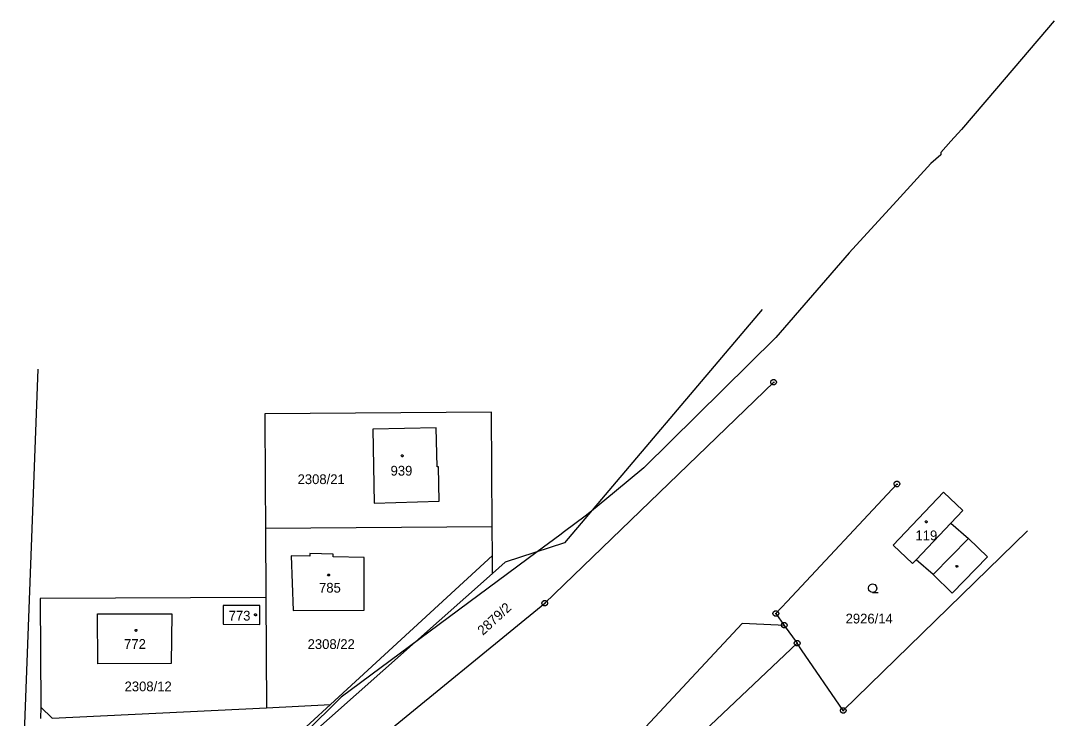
# Model space of a CAD drawing. Extents: x -760611 to -758411, y -1176479 to -1174807.
# Drawn here: x -758591.4 to -758411.4, y -1174928.5 to -1174806.9 of the extents above; entities that cross this region are included whole.
import ezdxf

# ---------------------------------------------------------------- set-up
doc = ezdxf.new("R2010")
doc.units = 0
for name, color, linetype in [('1', 7, 'Continuous'), ('11', 7, 'Continuous'), ('12', 7, 'Continuous'), ('2', 7, 'Continuous'), ('3', 7, 'Continuous'), ('4', 7, 'Continuous'), ('5', 7, 'Continuous'), ('8', 7, 'Continuous')]:
    doc.layers.add(name, color=color, linetype=linetype)

msp = doc.modelspace()

# ---------------------------------------------------------------- linework, layer by layer
at = {"layer": '1'}
for p, q in [((-758462.28, -1174857.27), (-758496.7, -1174897.94)), ((-758591.43, -1174949.22), (-758588.38, -1174867.67)), ((-758500.14, -1174908.44), (-758460.25, -1174869.94)), ((-758509.4, -1174875.14), (-758548.88, -1174875.41)), ((-758548.88, -1174875.41), (-758548.81, -1174887.41)), ((-758509.28, -1174895.15), (-758509.4, -1174875.14)), ((-758519.02, -1174877.9), (-758530.07, -1174878.13)), ((-758530.07, -1174878.13), (-758529.83, -1174890.98)), ((-758518.9, -1174884.67), (-758519.02, -1174877.9)), ((-758518.66, -1174884.67), (-758518.9, -1174884.67)), ((-758518.54, -1174890.66), (-758518.66, -1174884.67)), ((-758548.81, -1174887.41), (-758548.77, -1174895.41)), ((-758438.77, -1174887.67), (-758457.92, -1174908.13)), ((-758439.43, -1174898.33), (-758430.69, -1174889.1)), ((-758430.69, -1174889.1), (-758427.32, -1174892.29)), ((-758529.83, -1174890.98), (-758518.54, -1174890.66)), ((-758427.32, -1174892.29), (-758429.41, -1174894.49)), ((-758509.28, -1174895.15), (-758548.77, -1174895.41)), ((-758548.77, -1174895.41), (-758548.7, -1174907.41)), ((-758509.25, -1174900.15), (-758509.28, -1174895.15)), ((-758429.41, -1174894.49), (-758426.31, -1174897.14)), ((-758416.04, -1174895.82), (-758448.12, -1174927.13)), ((-758426.31, -1174897.14), (-758423, -1174900.38)), ((-758496.7, -1174897.94), (-758507.04, -1174901.3)), ((-758436.07, -1174901.52), (-758439.43, -1174898.33)), ((-758541.08, -1174900.26), (-758544.33, -1174900.19)), ((-758544.33, -1174900.19), (-758543.94, -1174909.68)), ((-758541.07, -1174899.78), (-758541.08, -1174900.26)), ((-758537.01, -1174899.88), (-758541.07, -1174899.78)), ((-758537.48, -1174926.06), (-758509.25, -1174900.15)), ((-758537.02, -1174900.36), (-758537.01, -1174899.88)), ((-758531.61, -1174900.48), (-758537.02, -1174900.36)), ((-758531.57, -1174909.63), (-758531.61, -1174900.48)), ((-758509.23, -1174903.24), (-758509.25, -1174900.15)), ((-758435.45, -1174900.87), (-758436.07, -1174901.52)), ((-758432.48, -1174903.46), (-758435.45, -1174900.87)), ((-758423, -1174900.38), (-758429.18, -1174906.69)), ((-758507.04, -1174901.3), (-758509.23, -1174903.24)), ((-758429.18, -1174906.69), (-758432.48, -1174903.46)), ((-758548.7, -1174907.41), (-758588.06, -1174907.59)), ((-758588.06, -1174907.59), (-758587.91, -1174926.56)), ((-758548.7, -1174907.41), (-758548.59, -1174926.64)), ((-758457.92, -1174908.13), (-758459.88, -1174910.23)), ((-758556.13, -1174908.84), (-758556.15, -1174912.09)), ((-758549.74, -1174908.83), (-758556.13, -1174908.84)), ((-758549.76, -1174912.13), (-758549.74, -1174908.83)), ((-758543.94, -1174909.68), (-758531.57, -1174909.63)), ((-758542.58, -1174943.09), (-758500.14, -1174908.44)), ((-758578.05, -1174910.27), (-758565.08, -1174910.27)), ((-758578.01, -1174919), (-758578.05, -1174910.27)), ((-758565.08, -1174910.27), (-758565.21, -1174918.94)), ((-758459.88, -1174910.23), (-758458.4, -1174912.29)), ((-758556.15, -1174912.09), (-758549.76, -1174912.13)), ((-758465.75, -1174911.99), (-758489.89, -1174937.8)), ((-758459.45, -1174912.25), (-758465.75, -1174911.99)), ((-758458.4, -1174912.29), (-758459.45, -1174912.25)), ((-758458.4, -1174912.29), (-758456.16, -1174915.41)), ((-758456.16, -1174915.41), (-758473.44, -1174931.75)), ((-758455.39, -1174916.53), (-758456.16, -1174915.41)), ((-758448.12, -1174927.13), (-758455.39, -1174916.53)), ((-758565.21, -1174918.94), (-758578.01, -1174919)), ((-758548.59, -1174926.64), (-758537.48, -1174926.06)), ((-758546.66, -1174934.51), (-758537.48, -1174926.06)), ((-758587.91, -1174926.56), (-758587.96, -1174928.54)), ((-758587.91, -1174926.56), (-758585.96, -1174928.44)), ((-758585.96, -1174928.44), (-758548.59, -1174926.64))]:
    msp.add_line(p, q, dxfattribs=at)
at = {"layer": '11'}
msp.add_lwpolyline([(-758411.36, -1174806.94), (-758421.45, -1174818.76), (-758427.54, -1174825.91), (-758429.37, -1174827.93), (-758431.14, -1174829.89), (-758431.14, -1174830.31), (-758432.86, -1174831.8), (-758438.19, -1174837.7), (-758447.12, -1174847.39), (-758459.9, -1174862.13), (-758482.88, -1174884.87), (-758487.98, -1174889.07), (-758492.01, -1174892.39), (-758493.08, -1174893.28), (-758496.7, -1174895.96), (-758497.52, -1174896.57), (-758501.45, -1174899.48), (-758535.6, -1174924.8), (-758541.98, -1174931.12)], dxfattribs=at)
at = {"layer": '12'}
for p, q in [((-758519.02, -1174877.9), (-758530.07, -1174878.13)), ((-758530.07, -1174878.13), (-758529.83, -1174890.98)), ((-758518.9, -1174884.67), (-758519.02, -1174877.9)), ((-758518.66, -1174884.67), (-758518.9, -1174884.67)), ((-758518.54, -1174890.66), (-758518.66, -1174884.67)), ((-758439.43, -1174898.33), (-758430.69, -1174889.1)), ((-758430.69, -1174889.1), (-758427.32, -1174892.29)), ((-758529.83, -1174890.98), (-758518.54, -1174890.66)), ((-758427.32, -1174892.29), (-758429.41, -1174894.49)), ((-758429.41, -1174894.49), (-758435.45, -1174900.87)), ((-758436.07, -1174901.52), (-758439.43, -1174898.33)), ((-758541.08, -1174900.26), (-758544.33, -1174900.19)), ((-758544.33, -1174900.19), (-758543.94, -1174909.68)), ((-758541.07, -1174899.78), (-758541.08, -1174900.26)), ((-758537.01, -1174899.88), (-758541.07, -1174899.78)), ((-758537.02, -1174900.36), (-758537.01, -1174899.88)), ((-758531.61, -1174900.48), (-758537.02, -1174900.36)), ((-758531.57, -1174909.63), (-758531.61, -1174900.48)), ((-758435.45, -1174900.87), (-758436.07, -1174901.52)), ((-758556.13, -1174908.84), (-758556.15, -1174912.09)), ((-758549.74, -1174908.83), (-758556.13, -1174908.84)), ((-758549.76, -1174912.13), (-758549.74, -1174908.83)), ((-758543.94, -1174909.68), (-758531.57, -1174909.63)), ((-758578.05, -1174910.27), (-758565.08, -1174910.27)), ((-758578.01, -1174919), (-758578.05, -1174910.27)), ((-758565.08, -1174910.27), (-758565.21, -1174918.94)), ((-758556.15, -1174912.09), (-758549.76, -1174912.13)), ((-758565.21, -1174918.94), (-758578.01, -1174919))]:
    msp.add_line(p, q, dxfattribs=at)
at = {"layer": '3'}
msp.add_lwpolyline([(-758443, -1174906.56), (-758443.38, -1174906.46), (-758443.65, -1174906.19), (-758443.75, -1174905.82), (-758443.65, -1174905.45), (-758443.38, -1174905.18), (-758443.01, -1174905.08), (-758442.64, -1174905.18), (-758442.37, -1174905.45), (-758442.27, -1174905.83), (-758442.37, -1174906.21), (-758442.64, -1174906.48), (-758443.02, -1174906.58), (-758442.02, -1174906.58)], dxfattribs=at)
at = {"layer": '4'}
for p, q in [((-758429.41, -1174894.49), (-758435.45, -1174900.87)), ((-758426.31, -1174897.14), (-758432.48, -1174903.46)), ((-758509.23, -1174903.24), (-758545.16, -1174935.1))]:
    msp.add_line(p, q, dxfattribs=at)
at = {"layer": '5'}
for points in [[(-758524.95, -1174882.58), (-758524.85, -1174882.6), (-758524.8, -1174882.69), (-758524.78, -1174882.75), (-758524.8, -1174882.84), (-758524.88, -1174882.91), (-758524.95, -1174882.92), (-758525.04, -1174882.89), (-758525.1, -1174882.83), (-758525.12, -1174882.75), (-758525.1, -1174882.66), (-758525.02, -1174882.59)], [(-758433.68, -1174894.08), (-758433.58, -1174894.1), (-758433.53, -1174894.19), (-758433.51, -1174894.25), (-758433.53, -1174894.34), (-758433.61, -1174894.41), (-758433.68, -1174894.42), (-758433.77, -1174894.39), (-758433.83, -1174894.33), (-758433.85, -1174894.25), (-758433.83, -1174894.16), (-758433.75, -1174894.09)], [(-758428.25, -1174901.88), (-758428.16, -1174902.03), (-758428.25, -1174902.18), (-758428.43, -1174902.18), (-758428.52, -1174902.03), (-758428.43, -1174901.88)], [(-758537.78, -1174903.35), (-758537.68, -1174903.37), (-758537.63, -1174903.46), (-758537.61, -1174903.52), (-758537.63, -1174903.61), (-758537.71, -1174903.68), (-758537.78, -1174903.69), (-758537.87, -1174903.66), (-758537.93, -1174903.6), (-758537.95, -1174903.52), (-758537.93, -1174903.43), (-758537.85, -1174903.36)], [(-758550.52, -1174910.29), (-758550.42, -1174910.31), (-758550.37, -1174910.4), (-758550.35, -1174910.46), (-758550.37, -1174910.55), (-758550.45, -1174910.62), (-758550.52, -1174910.63), (-758550.61, -1174910.6), (-758550.67, -1174910.54), (-758550.69, -1174910.46), (-758550.67, -1174910.37), (-758550.59, -1174910.3)], [(-758571.32, -1174913), (-758571.22, -1174913.02), (-758571.17, -1174913.11), (-758571.15, -1174913.17), (-758571.17, -1174913.26), (-758571.25, -1174913.33), (-758571.32, -1174913.34), (-758571.41, -1174913.31), (-758571.47, -1174913.25), (-758571.49, -1174913.17), (-758571.47, -1174913.08), (-758571.39, -1174913.01)]]:
    msp.add_lwpolyline(points, close=True, dxfattribs=at)
at = {"layer": '8'}
for p, q in [((-758460.37, -1174869.94), (-758460.13, -1174869.94)), ((-758438.89, -1174887.67), (-758438.65, -1174887.67)), ((-758500.26, -1174908.44), (-758500.02, -1174908.44)), ((-758460, -1174910.23), (-758459.76, -1174910.23)), ((-758458.52, -1174912.29), (-758458.28, -1174912.29)), ((-758456.28, -1174915.41), (-758456.04, -1174915.41)), ((-758448.24, -1174927.13), (-758448, -1174927.13))]:
    msp.add_line(p, q, dxfattribs=at)
for points in [[(-758460.1, -1174869.46), (-758459.85, -1174869.64), (-758459.75, -1174869.93), (-758459.85, -1174870.22), (-758460.1, -1174870.4), (-758460.41, -1174870.4), (-758460.66, -1174870.22), (-758460.76, -1174869.93), (-758460.66, -1174869.64), (-758460.41, -1174869.46)], [(-758438.62, -1174887.19), (-758438.37, -1174887.37), (-758438.27, -1174887.66), (-758438.37, -1174887.95), (-758438.62, -1174888.13), (-758438.93, -1174888.13), (-758439.18, -1174887.95), (-758439.28, -1174887.66), (-758439.18, -1174887.37), (-758438.93, -1174887.19)], [(-758499.99, -1174907.96), (-758499.74, -1174908.14), (-758499.64, -1174908.43), (-758499.74, -1174908.72), (-758499.99, -1174908.9), (-758500.3, -1174908.9), (-758500.55, -1174908.72), (-758500.65, -1174908.43), (-758500.55, -1174908.14), (-758500.3, -1174907.96)], [(-758459.73, -1174909.75), (-758459.48, -1174909.93), (-758459.38, -1174910.22), (-758459.48, -1174910.51), (-758459.73, -1174910.69), (-758460.04, -1174910.69), (-758460.29, -1174910.51), (-758460.39, -1174910.22), (-758460.29, -1174909.93), (-758460.04, -1174909.75)], [(-758458.25, -1174911.81), (-758458, -1174911.99), (-758457.9, -1174912.28), (-758458, -1174912.57), (-758458.25, -1174912.75), (-758458.56, -1174912.75), (-758458.81, -1174912.57), (-758458.91, -1174912.28), (-758458.81, -1174911.99), (-758458.56, -1174911.81)], [(-758456.01, -1174914.93), (-758455.76, -1174915.11), (-758455.66, -1174915.4), (-758455.76, -1174915.69), (-758456.01, -1174915.87), (-758456.32, -1174915.87), (-758456.57, -1174915.69), (-758456.67, -1174915.4), (-758456.57, -1174915.11), (-758456.32, -1174914.93)], [(-758447.97, -1174926.65), (-758447.72, -1174926.83), (-758447.62, -1174927.12), (-758447.72, -1174927.41), (-758447.97, -1174927.59), (-758448.28, -1174927.59), (-758448.53, -1174927.41), (-758448.63, -1174927.12), (-758448.53, -1174926.83), (-758448.28, -1174926.65)]]:
    msp.add_lwpolyline(points, close=True, dxfattribs=at)

# ---------------------------------------------------------------- texts
at = {"layer": '2'}
for s, p in [('939', (-758526.99, -1174886.2)), ('2308/21', (-758543.19, -1174887.68)), ('119', (-758435.55, -1174897.46)), ('785', (-758539.45, -1174906.59)), ('773', (-758555.2, -1174911.46)), ('2926/14', (-758447.72, -1174911.96)), ('772', (-758573.41, -1174916.39)), ('2308/22', (-758541.44, -1174916.41)), ('2308/12', (-758573.33, -1174923.78))]:
    msp.add_text(s, height=1.7, dxfattribs=at).set_placement(p)
msp.add_text('2879/2', height=1.7, rotation=42.7427, dxfattribs=at).set_placement((-758510.9, -1174914.13))

doc.saveas('drawing.dxf')
